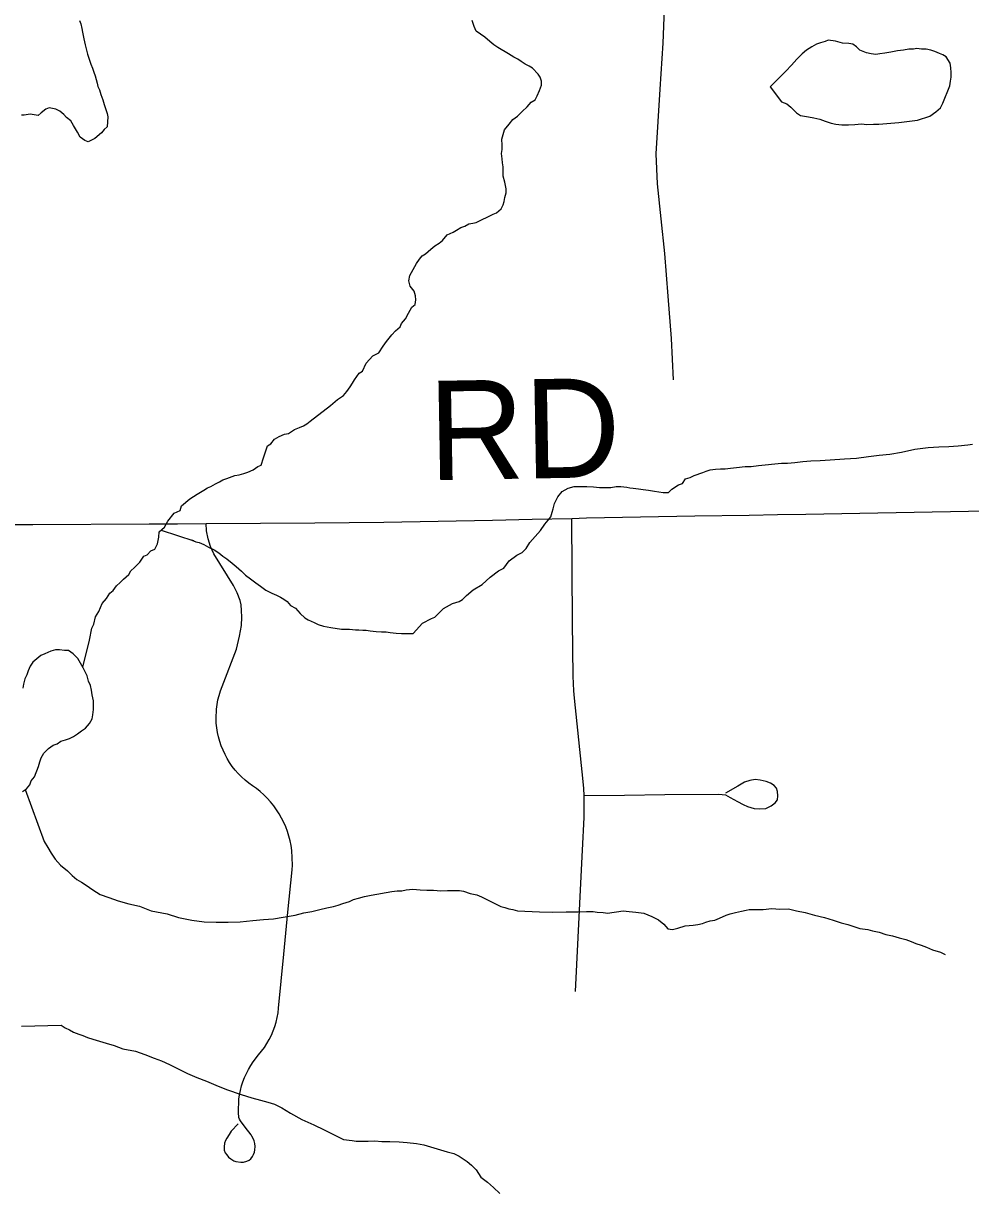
# Model space of a CAD drawing. Extents: x -11.4 to 84.1, y 11.1 to 59.
# Drawn here: x 26.651 to 27.193, y 44.72 to 45.388 of the extents above; entities that cross this region are included whole.
import ezdxf

# ---------------------------------------------------------------- set-up
doc = ezdxf.new("R2010")
doc.units = 0
for name, color, linetype in [('GM_X_Minor_Lake', 7, 'Continuous'), ('GM_X_Minor_River', 7, 'Continuous'), ('GM_X_Township_Road', 7, 'Continuous'), ('GM_X_Township_Road_Text', 7, 'Continuous')]:
    doc.layers.add(name, color=color, linetype=linetype)

msp = doc.modelspace()

# ---------------------------------------------------------------- linework, layer by layer
at = {"layer": 'GM_X_Minor_Lake'}
for points in [[(27.08611, 45.34261), (27.0877, 45.34204), (27.09001, 45.34018), (27.09311, 45.33681), (27.09541, 45.33532), (27.0977, 45.33498), (27.09998, 45.33464), (27.10303, 45.33393), (27.10646, 45.33323), (27.10952, 45.33213), (27.11296, 45.33105), (27.11563, 45.33033), (27.11905, 45.33001), (27.12285, 45.33007), (27.12665, 45.33013), (27.13044, 45.33058), (27.13348, 45.33025), (27.13728, 45.33031), (27.14032, 45.33036), (27.14487, 45.33081), (27.1517, 45.33131), (27.16231, 45.33262), (27.16949, 45.33502), (27.17286, 45.33736), (27.17548, 45.33968), (27.17696, 45.34237), (27.18097, 45.35232), (27.18131, 45.35499), (27.18165, 45.35728), (27.1816, 45.35994), (27.18156, 45.3626), (27.18113, 45.36525), (27.17879, 45.36902), (27.17687, 45.37013), (27.17496, 45.37086), (27.17228, 45.37195), (27.16999, 45.37267), (27.16732, 45.37339), (27.16466, 45.37335), (27.162, 45.37369), (27.16011, 45.37327), (27.15745, 45.37323), (27.15442, 45.3728), (27.15101, 45.37236), (27.14722, 45.37154), (27.14381, 45.3711), (27.14078, 45.37067), (27.13851, 45.37026), (27.13584, 45.37059), (27.13317, 45.37131), (27.12935, 45.37277), (27.12742, 45.37464), (27.1255, 45.37613), (27.12321, 45.37647), (27.11941, 45.37679), (27.11559, 45.37787), (27.1114, 45.37856), (27.10951, 45.37777), (27.10687, 45.37696), (27.1046, 45.37616), (27.10197, 45.3746), (27.09897, 45.37265), (27.09634, 45.3707), (27.09335, 45.36761), (27.09037, 45.36414), (27.08701, 45.36067), (27.07804, 45.35177)], [(27.07804, 45.35177), (27.08465, 45.34313), (27.08611, 45.34261)], [(26.65041, 44.94842), (26.65269, 44.94992), (26.65459, 44.9522), (26.65536, 44.95447), (26.65726, 44.95674), (26.65956, 44.9628), (26.66032, 44.96546), (26.66109, 44.96773), (26.66261, 44.97038), (26.66528, 44.97303), (26.66793, 44.97492), (26.67021, 44.97567), (26.67249, 44.97718), (26.67515, 44.97793), (26.67742, 44.97868), (26.6797, 44.97981), (26.68198, 44.98132), (26.68426, 44.98321), (26.68654, 44.98472), (26.68882, 44.98737), (26.69034, 44.99002), (26.69073, 44.99229), (26.69112, 44.99533), (26.69113, 44.99798), (26.69114, 45.00026), (26.69039, 45.00368), (26.69002, 45.00633), (26.68928, 45.00899), (26.68815, 45.01165), (26.6874, 45.01469), (26.68515, 45.01925), (26.68213, 45.02458), (26.67949, 45.02724), (26.67685, 45.02915), (26.67458, 45.02915), (26.67154, 45.02954), (26.66927, 45.02955), (26.66662, 45.0288), (26.6632, 45.0273), (26.66093, 45.02617), (26.65636, 45.02239), (26.65484, 45.02012), (26.65369, 45.01746), (26.65293, 45.01519), (26.65178, 45.01292), (26.65101, 45.00988), (26.65063, 45.00761)]]:
    msp.add_lwpolyline(points, dxfattribs=at)
at = {"layer": 'GM_X_Minor_River'}
for points in [[(26.68314, 45.38976), (26.68393, 45.38788), (26.68436, 45.38522), (26.68478, 45.38295), (26.6856, 45.37916), (26.68641, 45.37575), (26.68683, 45.37347), (26.68764, 45.37045), (26.68964, 45.36477), (26.69043, 45.36251), (26.69123, 45.36024), (26.69203, 45.35797), (26.69324, 45.35381), (26.69365, 45.35191), (26.69444, 45.35002), (26.69525, 45.34738), (26.69644, 45.34435), (26.69724, 45.3417), (26.69804, 45.33944), (26.69885, 45.33641), (26.69926, 45.33451), (26.69898, 45.3288), (26.69711, 45.32725), (26.69562, 45.32533), (26.69187, 45.32222), (26.68811, 45.32026), (26.6862, 45.32099), (26.6835, 45.32285), (26.68194, 45.32586), (26.68076, 45.32774), (26.67959, 45.32963), (26.67803, 45.33226), (26.67572, 45.33413), (26.67417, 45.336), (26.67186, 45.33786), (26.66956, 45.33897), (26.66575, 45.33967), (26.66386, 45.33888), (26.66124, 45.33693), (26.65936, 45.33538), (26.6548, 45.33606), (26.65139, 45.33563), (26.64987, 45.3356)], [(26.90578, 45.27327), (26.90805, 45.27368), (26.90994, 45.27409), (26.91296, 45.27567), (26.91673, 45.27725), (26.91974, 45.27882), (26.92163, 45.27961), (26.92425, 45.28194), (26.92535, 45.28424), (26.92607, 45.28615), (26.92642, 45.28843), (26.92713, 45.29111), (26.92709, 45.29339), (26.92668, 45.29528), (26.92627, 45.29718), (26.92545, 45.30059), (26.92541, 45.30325), (26.92536, 45.30591), (26.92494, 45.30818), (26.92491, 45.31046), (26.92447, 45.3135), (26.92482, 45.31579), (26.92477, 45.31845), (26.92472, 45.32187), (26.92614, 45.32722), (26.92875, 45.3303), (26.93099, 45.333), (26.93361, 45.33494), (26.93622, 45.33765), (26.93922, 45.34036), (26.94145, 45.34306), (26.94371, 45.34424), (26.94481, 45.34654), (26.94628, 45.3496), (26.94737, 45.35266), (26.94733, 45.35494), (26.94653, 45.35721), (26.94536, 45.35909), (26.94227, 45.36247), (26.94035, 45.36358), (26.93805, 45.36468), (26.93575, 45.36616), (26.93382, 45.36765), (26.93153, 45.36875), (26.92845, 45.3706), (26.92654, 45.37171), (26.92423, 45.3732), (26.92232, 45.37431), (26.92001, 45.37579), (26.9177, 45.37765), (26.915, 45.38027), (26.91, 45.38361), (26.90882, 45.38625), (26.90762, 45.38965)], [(26.68496, 45.01958), (26.68872, 45.03508), (26.69012, 45.04195), (26.69122, 45.04424), (26.69229, 45.04845), (26.69414, 45.05152), (26.69596, 45.05611), (26.69857, 45.05881), (26.70042, 45.06189), (26.70229, 45.06344), (26.70415, 45.06613), (26.70639, 45.06807), (26.70826, 45.07), (26.71125, 45.07271), (26.71236, 45.07463), (26.71461, 45.07657), (26.7176, 45.07966), (26.71982, 45.08312), (26.7217, 45.08391), (26.72394, 45.08623), (26.72621, 45.08703), (26.72768, 45.09009), (26.72837, 45.09391), (26.7287, 45.09696), (26.73169, 45.09967), (26.73353, 45.10312), (26.73725, 45.10774), (26.74065, 45.10932), (26.74136, 45.11199), (26.74623, 45.11588), (26.75037, 45.11861), (26.75412, 45.12095), (26.75638, 45.12213), (26.75827, 45.12292), (26.7609, 45.12449), (26.76316, 45.12566), (26.76504, 45.12683), (26.76731, 45.12763), (26.77184, 45.12923), (26.77449, 45.12965), (26.77713, 45.13045), (26.7794, 45.13125), (26.78242, 45.13244), (26.78504, 45.13439), (26.78693, 45.13518), (26.78838, 45.13938), (26.78946, 45.14282), (26.79054, 45.14627), (26.79242, 45.14744), (26.79466, 45.15014), (26.79729, 45.1517), (26.80031, 45.15289), (26.80258, 45.15331), (26.80596, 45.15565), (26.80898, 45.15684), (26.81124, 45.15763), (26.81312, 45.15881), (26.815, 45.16036), (26.82662, 45.16929), (26.83074, 45.17278), (26.83412, 45.17512), (26.83598, 45.17743), (26.83783, 45.18013), (26.83932, 45.18205), (26.84043, 45.18397), (26.84302, 45.18782), (26.8449, 45.18899), (26.8471, 45.19359), (26.85083, 45.19783), (26.85422, 45.19941), (26.85682, 45.20325), (26.85867, 45.20595), (26.86016, 45.20787), (26.86165, 45.2098), (26.86389, 45.21212), (26.8665, 45.21444), (26.86723, 45.21635), (26.86947, 45.21905), (26.87131, 45.22212), (26.87315, 45.22558), (26.87503, 45.22713), (26.87536, 45.2298), (26.87533, 45.23208), (26.87452, 45.23473), (26.87219, 45.23773), (26.87138, 45.24076), (26.87209, 45.24381), (26.87577, 45.25072), (26.87763, 45.25303), (26.87912, 45.25495), (26.881, 45.25613), (26.88399, 45.25884), (26.88624, 45.26077), (26.88887, 45.26234), (26.89074, 45.26389), (26.89335, 45.26698), (26.89674, 45.26855), (26.89862, 45.26973), (26.90125, 45.27129), (26.90352, 45.27209), (26.90578, 45.27327)], [(27.03468, 45.12937), (27.03959, 45.13097), (27.04148, 45.13176), (27.04374, 45.13256), (27.04677, 45.13299), (27.04981, 45.13304), (27.05247, 45.13308), (27.0555, 45.13351), (27.05891, 45.13395), (27.06384, 45.13441), (27.06726, 45.13447), (27.07143, 45.13492), (27.0847, 45.13627), (27.08812, 45.13633), (27.09229, 45.13678), (27.09684, 45.13724), (27.10139, 45.13769), (27.1067, 45.13778), (27.1124, 45.13825), (27.12074, 45.13877), (27.12757, 45.13926), (27.13439, 45.14013), (27.14046, 45.14099), (27.14653, 45.14147), (27.15334, 45.14273), (27.16091, 45.14437), (27.16849, 45.14526), (27.17456, 45.14574), (27.18026, 45.14583), (27.18557, 45.1463), (27.19126, 45.14677), (27.19391, 45.1472)], [(26.72974, 45.0979), (26.74853, 45.09196), (26.74739, 45.09232), (26.74969, 45.09122), (26.75159, 45.09087), (26.75427, 45.08977), (26.75695, 45.08829), (26.76002, 45.08682), (26.76271, 45.08497), (26.76502, 45.0831), (26.76732, 45.08162), (26.7704, 45.07901), (26.77271, 45.07715), (26.77579, 45.07453), (26.77811, 45.07229), (26.78081, 45.07005), (26.78388, 45.06782), (26.78658, 45.06597), (26.78965, 45.06374), (26.7931, 45.06189), (26.79578, 45.06079), (26.79808, 45.05969), (26.79999, 45.05858), (26.80192, 45.05709), (26.80385, 45.05484), (26.80654, 45.05337), (26.80925, 45.05037), (26.81195, 45.04775), (26.81387, 45.04664), (26.81731, 45.04518), (26.81961, 45.04407), (26.82266, 45.04298), (26.82685, 45.04229), (26.83295, 45.04125), (26.8375, 45.04133), (26.84093, 45.041), (26.84283, 45.04103), (26.84511, 45.04069), (26.84701, 45.04072), (26.8493, 45.04038), (26.85272, 45.04006), (26.85576, 45.03973), (26.85842, 45.03977), (26.86071, 45.03943), (26.86413, 45.0391), (26.86718, 45.03877), (26.87401, 45.03888), (26.87923, 45.04467), (26.8845, 45.04742), (26.88639, 45.04821), (26.89124, 45.05324), (26.89651, 45.05599), (26.90029, 45.05719), (26.90217, 45.05836), (26.90441, 45.06068), (26.90816, 45.06378), (26.91342, 45.06691), (26.91791, 45.07117), (26.92279, 45.07467), (26.9258, 45.07624), (26.92877, 45.08047), (26.93327, 45.08359), (26.93629, 45.08516), (26.93852, 45.08748), (26.94075, 45.09094), (26.94373, 45.09441), (26.94671, 45.09788), (26.94931, 45.10134), (26.95117, 45.10366), (26.95266, 45.10558), (26.95337, 45.10826), (26.9541, 45.11017), (26.95481, 45.11322), (26.95664, 45.11706), (26.95925, 45.12014), (26.96263, 45.1221), (26.96604, 45.12291), (26.96832, 45.12295), (26.97059, 45.12299), (26.97325, 45.12303), (26.97706, 45.12272), (26.98048, 45.12239), (26.9839, 45.12245), (26.98693, 45.1225), (26.98997, 45.12293), (26.99262, 45.12297), (26.99605, 45.12265), (26.99795, 45.1223), (26.99986, 45.12195), (27.0029, 45.12162), (27.00557, 45.12128), (27.00861, 45.12095), (27.01204, 45.12025), (27.01699, 45.11957), (27.02003, 45.11962), (27.0219, 45.12155), (27.02565, 45.1239), (27.02792, 45.12469), (27.02977, 45.12738), (27.03242, 45.12819), (27.03468, 45.12937)], [(26.65204, 44.94949), (26.66292, 44.91982), (26.66488, 44.91642), (26.66684, 44.91303), (26.66917, 44.90965), (26.67227, 44.90628), (26.67612, 44.90292), (26.67883, 44.9003), (26.68152, 44.89807), (26.6842, 44.89659), (26.6869, 44.89473), (26.69074, 44.89213), (26.69496, 44.88954), (26.69993, 44.88772), (26.70527, 44.88591), (26.71138, 44.88411), (26.71748, 44.88269), (26.72398, 44.88013), (26.73313, 44.87838), (26.73962, 44.87621), (26.74724, 44.87481), (26.75447, 44.87379), (26.76132, 44.87352), (26.76815, 44.87363), (26.77499, 44.87375), (26.78219, 44.87462), (26.78826, 44.8751), (26.79395, 44.87558), (26.79963, 44.87643), (26.80645, 44.87769), (26.81136, 44.87891), (26.81591, 44.87974), (26.82045, 44.88096), (26.82461, 44.88179), (26.8284, 44.88261), (26.83104, 44.88341), (26.83369, 44.88422), (26.83746, 44.88542), (26.83972, 44.8866), (26.84275, 44.88741), (26.84615, 44.88823), (26.84994, 44.88905), (26.86168, 44.89114), (26.86471, 44.89157), (26.86737, 44.89162), (26.87002, 44.89204), (26.87381, 44.89248), (26.87799, 44.89217), (26.8818, 44.89185), (26.88559, 44.89192), (26.88978, 44.8916), (26.89358, 44.89167), (26.89661, 44.89172), (26.89851, 44.89175), (26.90041, 44.89178), (26.90269, 44.89144), (26.90652, 44.88998), (26.91033, 44.88928), (26.913, 44.88818), (26.91569, 44.88671), (26.91875, 44.88524), (26.92181, 44.88377), (26.92411, 44.88266), (26.9264, 44.88194), (26.92869, 44.88122), (26.93098, 44.88088), (26.93365, 44.88016), (26.93783, 44.87985), (26.94619, 44.8796), (26.95379, 44.87935), (26.96139, 44.87947), (26.96822, 44.87958), (26.97316, 44.87967), (26.97696, 44.87973), (26.97924, 44.87939), (26.98266, 44.87906), (26.98533, 44.87873), (26.9876, 44.87914), (26.99025, 44.87957), (26.99404, 44.88001), (26.99747, 44.87969), (27.00127, 44.87937), (27.00584, 44.87868), (27.01043, 44.87686), (27.01426, 44.87502), (27.01734, 44.87241), (27.01967, 44.86978), (27.02233, 44.86945), (27.02536, 44.87026), (27.02951, 44.87147), (27.03406, 44.87192), (27.03671, 44.87235), (27.03937, 44.87277), (27.04125, 44.87356), (27.0439, 44.87437), (27.04655, 44.87479), (27.04919, 44.87597), (27.05296, 44.87756)], [(27.05296, 44.87756), (27.05522, 44.87835), (27.05825, 44.87917), (27.06165, 44.87998), (27.06431, 44.8804), (27.0662, 44.88082), (27.06848, 44.88085), (27.07114, 44.8809), (27.07417, 44.88095), (27.0791, 44.88141), (27.08367, 44.8811), (27.0886, 44.88119), (27.09318, 44.88012), (27.09813, 44.87906), (27.10348, 44.87763), (27.1092, 44.8762), (27.11416, 44.87476), (27.11874, 44.87331), (27.12256, 44.87224), (27.126, 44.87115), (27.12943, 44.87007), (27.134, 44.86938), (27.13667, 44.86867), (27.13858, 44.86832), (27.14048, 44.86797), (27.1443, 44.86651), (27.14811, 44.86581), (27.15193, 44.86473), (27.15575, 44.86366), (27.1588, 44.86257), (27.16148, 44.86147), (27.16454, 44.86038), (27.1676, 44.85929), (27.17104, 44.85782), (27.17562, 44.85638), (27.17792, 44.85527), (27.17818, 44.8552)], [(26.64986, 44.81407), (26.67267, 44.81464), (26.67497, 44.81316), (26.67727, 44.81206), (26.67957, 44.81057), (26.68263, 44.80948), (26.68492, 44.80876), (26.6876, 44.80766), (26.69065, 44.80657), (26.69447, 44.8055), (26.69829, 44.80442), (26.70287, 44.80297), (26.70784, 44.80115), (26.71508, 44.79975), (26.72043, 44.79794), (26.72578, 44.79574), (26.72998, 44.79429), (26.73458, 44.79209), (26.73994, 44.78951), (26.74492, 44.78693), (26.75027, 44.78474), (26.75563, 44.78255), (26.76098, 44.78035), (26.7671, 44.77779), (26.77551, 44.77489), (26.78162, 44.77309), (26.78658, 44.77165), (26.79077, 44.77058), (26.79459, 44.7695), (26.7988, 44.76729), (26.80379, 44.76432), (26.81031, 44.76063), (26.8172, 44.7577), (26.82294, 44.75475), (26.82869, 44.75181), (26.83405, 44.74923), (26.839, 44.74855), (26.84129, 44.74821), (26.84356, 44.74825), (26.84812, 44.74832), (26.85192, 44.74838), (26.8561, 44.74807), (26.86066, 44.74815), (26.86598, 44.74785), (26.87054, 44.74755), (26.87587, 44.74688), (26.88006, 44.74619), (26.89342, 44.74222), (26.89724, 44.74115), (26.9003, 44.73967), (26.90261, 44.73819), (26.90491, 44.73671), (26.90723, 44.73446), (26.90993, 44.73185), (26.91266, 44.72771), (26.91651, 44.72473), (26.91997, 44.72175), (26.92345, 44.71838)]]:
    msp.add_lwpolyline(points, dxfattribs=at)
at = {"layer": 'GM_X_Township_Road'}
for points in [[(27.02279, 45.18399), (27.02162, 45.20767), (27.01979, 45.232), (27.01797, 45.25633), (27.0158, 45.27624), (27.01364, 45.29616), (27.01291, 45.31344), (27.01405, 45.33195), (27.01519, 45.35046), (27.01692, 45.37675), (27.01782, 45.40131)], [(26.62537, 45.1012), (26.65643, 45.1013), (26.72285, 45.10159), (26.73916, 45.10169), (26.75547, 45.10179), (26.78654, 45.10202), (26.81761, 45.10225), (26.83738, 45.10239), (26.85714, 45.10253), (26.8882, 45.10316), (26.91926, 45.10379), (26.94197, 45.10425), (26.96468, 45.10471), (26.97298, 45.10506), (27.00404, 45.10559), (27.0351, 45.10612), (27.06617, 45.10665), (27.0823, 45.10692), (27.09844, 45.10719), (27.1295, 45.10772), (27.16056, 45.10825), (27.19163, 45.10878), (27.22269, 45.1093)], [(26.96675, 44.83385), (26.96828, 44.86488), (26.96982, 44.89591), (26.97075, 44.91474), (26.97167, 44.93358), (26.97182, 44.93776), (26.97168, 44.94611), (26.97149, 44.95011), (26.97111, 44.9541), (26.96866, 44.978), (26.96621, 45.00191), (26.96583, 45.00605), (26.96555, 45.0102), (26.9654, 45.01436), (26.96516, 45.04543), (26.96492, 45.07507), (26.96468, 45.10471)], [(26.77376, 44.75822), (26.76989, 44.7539), (26.76864, 44.75205), (26.7673, 44.75007), (26.76653, 44.74856), (26.76599, 44.74704), (26.76575, 44.74498), (26.76591, 44.74314), (26.7664, 44.74165), (26.7673, 44.74046), (26.76834, 44.73915), (26.76957, 44.73808), (26.77133, 44.73709), (26.77249, 44.73668), (26.77528, 44.7362), (26.7768, 44.73627), (26.77873, 44.73673), (26.78005, 44.73738), (26.78099, 44.73812), (26.78206, 44.73943), (26.78268, 44.74063), (26.78321, 44.7419), (26.78338, 44.74338), (26.7835, 44.74527), (26.78334, 44.74692), (26.78296, 44.74839), (26.78243, 44.74971), (26.78173, 44.75107), (26.78122, 44.75184), (26.77992, 44.75361), (26.77832, 44.75555), (26.7751, 44.75996), (26.77458, 44.76093), (26.7743, 44.76188), (26.77398, 44.76458), (26.77426, 44.77228), (26.77465, 44.77482), (26.77512, 44.77734), (26.77579, 44.77984), (26.77659, 44.78228), (26.7775, 44.78469), (26.77854, 44.78703), (26.77973, 44.78932), (26.78101, 44.79154), (26.78242, 44.7937), (26.78555, 44.79775), (26.78726, 44.79981), (26.78882, 44.80196), (26.7903, 44.80421), (26.79163, 44.80654), (26.79281, 44.80892), (26.79385, 44.81138), (26.7948, 44.81389), (26.79556, 44.81645), (26.79617, 44.81904), (26.79665, 44.82167), (26.79698, 44.82433), (26.79998, 44.85525), (26.80231, 44.8794), (26.80465, 44.90355), (26.80484, 44.90633), (26.80451, 44.9147), (26.80413, 44.91746), (26.80357, 44.92019), (26.8029, 44.92289), (26.80205, 44.92556), (26.80106, 44.92818), (26.79992, 44.93074), (26.79869, 44.93323), (26.79732, 44.93565), (26.7958, 44.938), (26.79415, 44.94025), (26.7924, 44.94243), (26.7905, 44.9445), (26.78856, 44.94647), (26.78647, 44.94833), (26.78429, 44.95007), (26.78202, 44.9517), (26.77984, 44.95326), (26.77776, 44.95494), (26.77577, 44.95675), (26.77392, 44.95865), (26.77212, 44.96065), (26.77047, 44.96277), (26.76895, 44.96496), (26.76758, 44.96725), (26.7663, 44.96959), (26.76516, 44.97202), (26.76417, 44.97449), (26.76332, 44.97703), (26.76256, 44.97961), (26.76204, 44.98222), (26.76161, 44.98486), (26.76133, 44.98752), (26.76124, 44.9902), (26.76143, 44.99554), (26.76176, 44.9982), (26.76224, 45.00083), (26.76291, 45.00342), (26.76366, 45.00599), (26.76461, 45.0085), (26.77279, 45.02989), (26.77454, 45.03739), (26.77581, 45.04333), (26.776, 45.04811), (26.77581, 45.052), (26.77559, 45.05534), (26.77501, 45.05769), (26.77335, 45.06209), (26.77113, 45.06625), (26.76, 45.08437), (26.75806, 45.08858), (26.75664, 45.09298), (26.75579, 45.09753), (26.75547, 45.10179)], [(26.97168, 44.94611), (26.99481, 44.94636), (27.01794, 44.94662), (27.04877, 44.94695), (27.05266, 44.94642), (27.0552, 44.94505), (27.05935, 44.94274), (27.06271, 44.94096), (27.06508, 44.93976), (27.06895, 44.93871), (27.07227, 44.93854), (27.07559, 44.93871), (27.0787, 44.94027), (27.08105, 44.94183), (27.08231, 44.94368), (27.08251, 44.94593), (27.08231, 44.94837), (27.08172, 44.95022), (27.08036, 44.95188), (27.07826, 44.95312), (27.07578, 44.95422), (27.07246, 44.9549), (27.06963, 44.95519), (27.06651, 44.95471), (27.06339, 44.95373), (27.05958, 44.95149), (27.05256, 44.94739)]]:
    msp.add_lwpolyline(points, dxfattribs=at)

# ---------------------------------------------------------------- texts
at = {"layer": 'GM_X_Township_Road_Text'}
msp.add_text('RD', height=0.056818, rotation=0.98724, dxfattribs=at).set_placement((26.88315, 45.12656))

doc.saveas('drawing.dxf')
